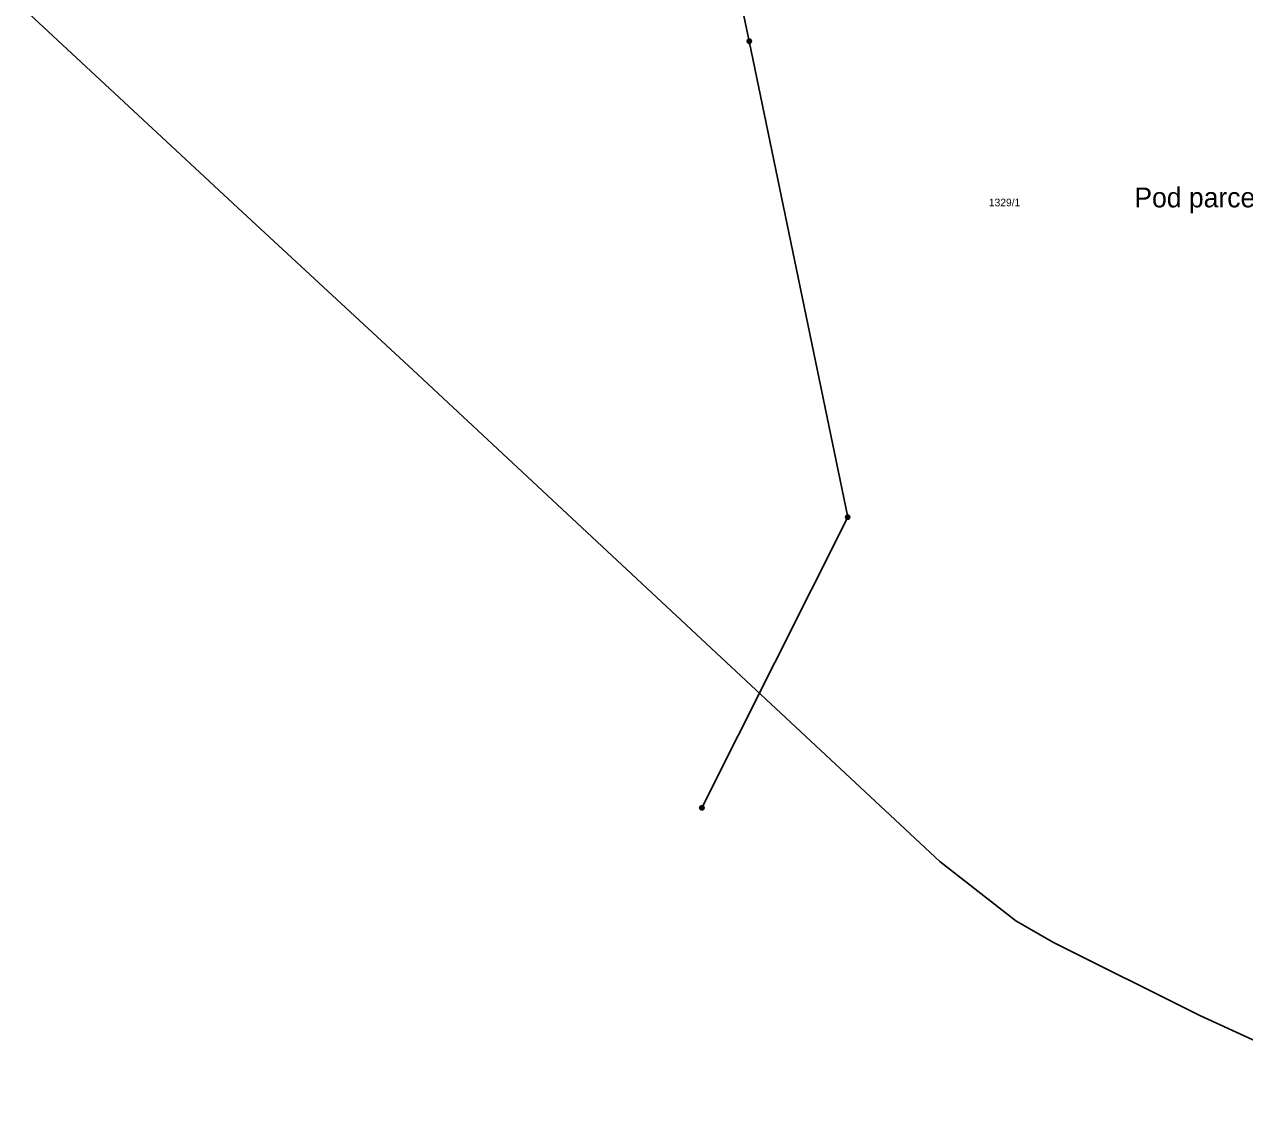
# Model space of a CAD drawing. Extents: x -789470 to -786707, y -1118640 to -1114455.
# Drawn here: x -787845.3 to -787574.7, y -1117267.6 to -1117025.8 of the extents above; entities that cross this region are included whole.
import ezdxf

# ---------------------------------------------------------------- set-up
doc = ezdxf.new("R2010")
doc.units = 0
for name, color, linetype in [('1', 7, 'Continuous'), ('2', 7, 'Continuous'), ('6', 7, 'Continuous'), ('7', 7, 'Continuous')]:
    doc.layers.add(name, color=color, linetype=linetype)

msp = doc.modelspace()

# ---------------------------------------------------------------- linework, layer by layer
at = {"layer": '1'}
for p, q in [((-787845.29, -1117022.51), (-787796.95, -1117067.42)), ((-787796.95, -1117067.42), (-787759.1, -1117102.45)), ((-787759.1, -1117102.45), (-787642.26, -1117211.42)), ((-787642.26, -1117211.42), (-787625.39, -1117224.6)), ((-787625.39, -1117224.6), (-787617.04, -1117229.4)), ((-787617.04, -1117229.4), (-787584.6, -1117245.63)), ((-787584.6, -1117245.63), (-787536.52, -1117267.58))]:
    msp.add_line(p, q, dxfattribs=at)
at = {"layer": '6'}
for p, q in [((-787684.51, -1117029.53), (-787706.26, -1116926.46)), ((-787662.69, -1117135.08), (-787684.51, -1117029.53)), ((-787695.02, -1117199.55), (-787662.69, -1117135.08))]:
    msp.add_line(p, q, dxfattribs=at)
for points in [[(-787684.66, -1117029.05), (-787684.35, -1117029.05), (-787684.1, -1117029.23), (-787684, -1117029.52), (-787684.1, -1117029.81), (-787684.35, -1117029.99), (-787684.66, -1117029.99), (-787684.91, -1117029.81), (-787685.01, -1117029.52), (-787684.91, -1117029.23), (-787684.66, -1117029.05), (-787684.63, -1117029.09), (-787684.39, -1117029.09), (-787684.23, -1117029.17), (-787684.79, -1117029.17), (-787684.87, -1117029.25), (-787684.15, -1117029.25), (-787684.15, -1117029.33), (-787684.87, -1117029.33), (-787684.91, -1117029.41), (-787684.11, -1117029.41), (-787684.07, -1117029.49), (-787684.95, -1117029.49), (-787684.95, -1117029.57), (-787684.07, -1117029.57), (-787684.1, -1117029.65), (-787684.91, -1117029.65), (-787684.9, -1117029.73), (-787684.09, -1117029.73), (-787684.14, -1117029.81), (-787684.86, -1117029.81), (-787684.78, -1117029.89), (-787684.22, -1117029.89), (-787684.33, -1117029.97), (-787684.67, -1117029.97)], [(-787662.84, -1117134.6), (-787662.53, -1117134.6), (-787662.28, -1117134.78), (-787662.18, -1117135.07), (-787662.28, -1117135.36), (-787662.53, -1117135.54), (-787662.84, -1117135.54), (-787663.09, -1117135.36), (-787663.19, -1117135.07), (-787663.09, -1117134.78), (-787662.84, -1117134.6), (-787662.81, -1117134.64), (-787662.57, -1117134.64), (-787662.41, -1117134.72), (-787662.97, -1117134.72), (-787663.05, -1117134.8), (-787662.33, -1117134.8), (-787662.33, -1117134.88), (-787663.05, -1117134.88), (-787663.09, -1117134.96), (-787662.29, -1117134.96), (-787662.25, -1117135.04), (-787663.13, -1117135.04), (-787663.13, -1117135.12), (-787662.25, -1117135.12), (-787662.28, -1117135.2), (-787663.09, -1117135.2), (-787663.08, -1117135.28), (-787662.27, -1117135.28), (-787662.32, -1117135.36), (-787663.04, -1117135.36), (-787662.96, -1117135.44), (-787662.4, -1117135.44), (-787662.51, -1117135.52), (-787662.85, -1117135.52)], [(-787695.17, -1117199.07), (-787694.86, -1117199.07), (-787694.61, -1117199.25), (-787694.51, -1117199.54), (-787694.61, -1117199.83), (-787694.86, -1117200.01), (-787695.17, -1117200.01), (-787695.42, -1117199.83), (-787695.52, -1117199.54), (-787695.42, -1117199.25), (-787695.17, -1117199.07), (-787695.14, -1117199.11), (-787694.9, -1117199.11), (-787694.74, -1117199.19), (-787695.3, -1117199.19), (-787695.38, -1117199.27), (-787694.66, -1117199.27), (-787694.66, -1117199.35), (-787695.38, -1117199.35), (-787695.42, -1117199.43), (-787694.62, -1117199.43), (-787694.58, -1117199.51), (-787695.46, -1117199.51), (-787695.46, -1117199.59), (-787694.58, -1117199.59), (-787694.61, -1117199.67), (-787695.42, -1117199.67), (-787695.41, -1117199.75), (-787694.6, -1117199.75), (-787694.65, -1117199.83), (-787695.37, -1117199.83), (-787695.29, -1117199.91), (-787694.73, -1117199.91), (-787694.84, -1117199.99), (-787695.18, -1117199.99)]]:
    msp.add_lwpolyline(points, dxfattribs=at)

# ---------------------------------------------------------------- texts
at = {"layer": '2'}
msp.add_text('1329/1', height=1.7, dxfattribs=at).set_placement((-787631.37, -1117066.13))
at = {"layer": '7'}
msp.add_text('Pod parcelami', height=4.4, dxfattribs=at).set_placement((-787599.11, -1117066.36))

doc.saveas('drawing.dxf')
